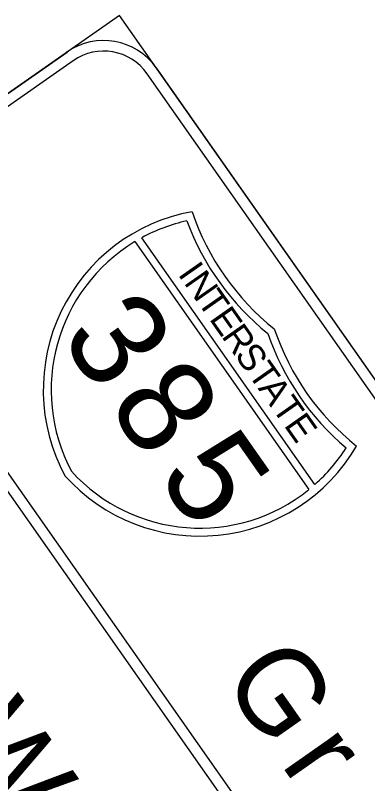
# Model space of a CAD drawing. Extents: x 1581789 to 1622364, y 1043167 to 1103486.
# Drawn here: x 1604383.95 to 1604405.99, y 1089050.53 to 1089098.61 of the extents above; entities that cross this region are included whole.
import ezdxf

# ---------------------------------------------------------------- set-up
doc = ezdxf.new("R2010")
doc.units = 0
doc.layers.add('RD_PD_PatLn2', color=7, linetype='Continuous')

msp = doc.modelspace()

# ---------------------------------------------------------------- linework, layer by layer
at = {"layer": 'RD_PD_PatLn2'}
for p, q in [((1604390.459, 1089098.61), (1604372.448, 1089085.977)), ((1604444.438, 1089021.654), (1604390.459, 1089098.61)), ((1604372.448, 1089085.977), (1604387.185, 1089096.313)), ((1604387.567, 1089095.767), (1604372.831, 1089085.431)), ((1604402.699, 1089069.26), (1604391.871, 1089084.697)), ((1604391.435, 1089084.448), (1604402.317, 1089068.935))]:
    msp.add_line(p, q, dxfattribs=at)
for points in [[(1604392.756, 1089095.335), (1604442.141, 1089024.928)], [(1604441.596, 1089024.546), (1604392.21, 1089094.952)], [(1604375.374, 1089081.515), (1604423.228, 1089013.291), (1604422.682, 1089012.908), (1604374.829, 1089081.132), (1604375.374, 1089081.515), (1604375.374, 1089081.515)]]:
    msp.add_lwpolyline(points, dxfattribs=at)
for centre, radius, start, end in [((1604389.481, 1089093.038), 4, 35.047, 125.0467), ((1604389.481, 1089093.038), 3.333, 35.047, 125.0467), ((1604397.031, 1089075.172), 11.333, 100.2938, 208.2906), ((1604410.154, 1089091.476), 16, 198.7892, 231.3046), ((1604397.031, 1089075.172), 10.833, 102.5352, 118.4456), ((1604410.14, 1089091.512), 16.5, 200.4502, 230.9327), ((1604397.028, 1089075.17), 10.833, 121.0824, 207.9783), ((1604415.298, 1089084.142), 16, 198.7892, 231.3046), ((1604415.327, 1089084.117), 16.5, 199.1611, 229.6436), ((1604395.5, 1089077.355), 11.333, 221.8032, 329.8), ((1604395.5, 1089077.355), 10.833, 311.648, 327.5586), ((1604395.497, 1089077.353), 10.833, 222.1155, 309.0114)]:
    msp.add_arc(centre, radius, start, end, dxfattribs=at)

# ---------------------------------------------------------------- texts
for s, height, p in [('I', 1.667, (1604394.087, 1089082.409)), ('N', 1.667, (1604394.461, 1089081.876)), ('T', 1.667, (1604395.283, 1089080.704)), ('3', 6, (1604386.673, 1089078.467)), ('E', 1.667, (1604396.046, 1089079.616)), ('R', 1.667, (1604396.809, 1089078.529)), ('S', 1.667, (1604397.631, 1089077.356)), ('T', 1.667, (1604398.454, 1089076.184)), ('8', 6, (1604389.634, 1089074.246)), ('A', 1.667, (1604399.097, 1089075.267)), ('T', 1.667, (1604399.956, 1089074.041)), ('E', 1.667, (1604400.719, 1089072.954)), ('5', 6, (1604392.757, 1089069.794)), ('G', 5.333, (1604396.785, 1089057.084)), ('W', 5.333, (1604379.73, 1089053.246)), ('r', 5.333, (1604400.506, 1089051.781))]:
    msp.add_text(s, height=height, rotation=305.0468, dxfattribs=at).set_placement(p)

doc.saveas('drawing.dxf')
